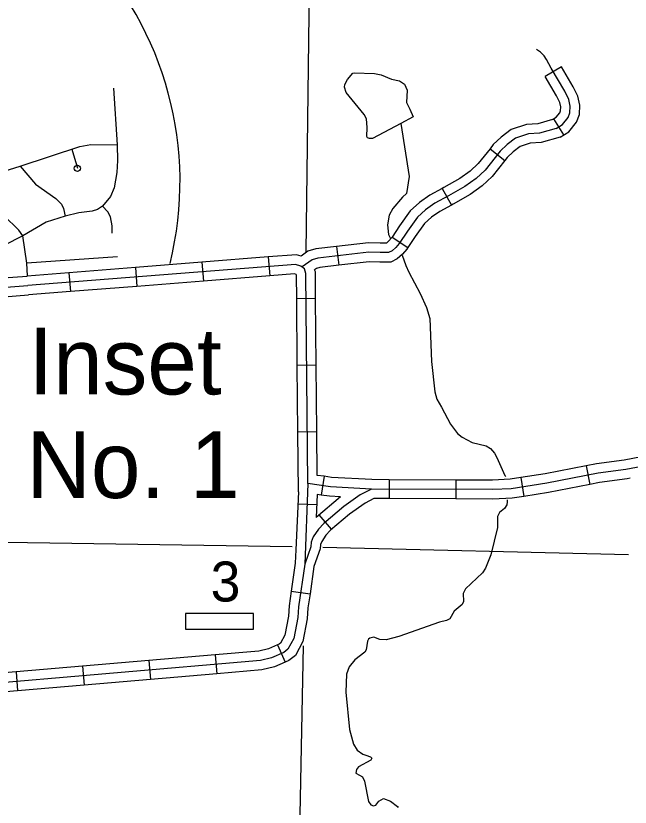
# Model space of a CAD drawing. Extents: x 1370567 to 1373900, y 377514 to 379648.
# Drawn here: x 1371923.2 to 1372062.3, y 377996 to 378175.1 of the extents above; entities that cross this region are included whole.
import ezdxf

# ---------------------------------------------------------------- set-up
doc = ezdxf.new("R2010")
doc.units = 0
doc.layers.add('Default', color=7, linetype='Continuous')

msp = doc.modelspace()

# ---------------------------------------------------------------- linework, layer by layer
at = {"layer": 'Default'}
for p, q in [((1372046.71, 378163.57), (1372043.03, 378161.37)), ((1372047.25, 378148.21), (1372044.99, 378151.85)), ((1372030.55, 378145.06), (1372033.9, 378142.39)), ((1372019.75, 378136.07), (1372021.8, 378132.31)), ((1372008.38, 378125.04), (1372011.96, 378122.68)), ((1371995.82, 378122.94), (1371996.31, 378118.68)), ((1371980.38, 378120.56), (1371980.72, 378116.28)), ((1371965.35, 378119.37), (1371965.68, 378115.1)), ((1371935.27, 378117), (1371935.6, 378112.73)), ((1371950.31, 378118.18), (1371950.64, 378113.91)), ((1371991.08, 378111.15), (1371986.8, 378111.11)), ((1371991.22, 378096.07), (1371986.93, 378096.03)), ((1371991.35, 378080.98), (1371987.06, 378080.94)), ((1372052.29, 378073.29), (1372053.12, 378069.09)), ((1371992.98, 378070.92), (1371992.37, 378066.68)), ((1372037.54, 378070.62), (1372038.19, 378066.38)), ((1372007.74, 378070.15), (1372007.72, 378065.87)), ((1372022.82, 378070.08), (1372022.8, 378065.8)), ((1371987.06, 378064.71), (1371991.34, 378064.52)), ((1371994.67, 378058.94), (1371991.91, 378062.22)), ((1371985.57, 378044.95), (1371989.81, 378044.34)), ((1371976.99, 378039.88), (1371961.63, 378039.88)), ((1371961.63, 378039.88), (1371961.63, 378036.31)), ((1371976.99, 378036.31), (1371976.99, 378039.88)), ((1371961.63, 378036.31), (1371976.99, 378036.31)), ((1371982.49, 378032.8), (1371984.18, 378028.86)), ((1371953.35, 378029.23), (1371953.72, 378024.96)), ((1371968.38, 378030.52), (1371968.75, 378026.25)), ((1371938.32, 378027.94), (1371938.68, 378023.67)), ((1371923.29, 378026.66), (1371923.65, 378022.39))]:
    msp.add_line(p, q, dxfattribs=at)
for points in [[(1371990.75, 378238.67), (1371989.89, 378205.51), (1371988.86, 378121.7)], [(1372045.54, 378149.67), (1372046.93, 378150.53), (1372048.26, 378152.11), (1372048.64, 378153.19), (1372048.7, 378154.71), (1372048.39, 378156.23), (1372047.5, 378158.06), (1372044.4, 378163.25), (1372043.33, 378165.27), (1372042.82, 378166.09), (1372042, 378166.92), (1372041.05, 378167.49)], [(1372046.41, 378147.69), (1372048.35, 378148.89), (1372050.15, 378151.03), (1372050.77, 378152.78), (1372050.85, 378154.88), (1372050.43, 378156.92), (1372049.39, 378159.08), (1372046.71, 378163.57)], [(1372010.39, 378150.78), (1372003.97, 378147.38), (1372003.27, 378147.35), (1372002.82, 378147.53), (1372002.65, 378147.82), (1372002.78, 378149.84), (1372002.57, 378151.81), (1372002.1, 378152.77), (1371997.98, 378157.8), (1371997.61, 378158.97), (1371997.71, 378159.57), (1371998.32, 378160.72), (1371999.52, 378162.17), (1371999.84, 378162.23), (1372004.41, 378162.06), (1372005.9, 378161.77), (1372008.24, 378160.79), (1372010.07, 378160.39), (1372011.17, 378159.67), (1372011.82, 378158.28), (1372011.68, 378155.48), (1372012.42, 378153.98), (1372013.13, 378152.28), (1372010.39, 378150.78), (1372012.27, 378138.8), (1372011.65, 378134.91), (1372010.73, 378134.06), (1372008.54, 378131.54), (1372007.72, 378130.01), (1372007.35, 378127.86), (1372007.54, 378125.64), (1372008.04, 378124.72)], [(1372044.67, 378151.65), (1372045.51, 378152.17), (1372046.37, 378153.19), (1372046.51, 378153.6), (1372046.55, 378154.53), (1372046.34, 378155.53), (1372045.61, 378157.04), (1372043.03, 378161.37)], [(1371945.37, 378158.76), (1371946.18, 378145.93), (1371946.25, 378142.39), (1371946.13, 378139.65), (1371945.47, 378136.24), (1371944.65, 378134.26), (1371942.89, 378132.03), (1371941.73, 378131.28), (1371940.5, 378130.92), (1371937.51, 378130.58), (1371934.42, 378129.79), (1371930.1, 378128.43), (1371924.82, 378125.37)], [(1372044.67, 378151.65), (1372041.36, 378150.72), (1372038.8, 378150.53), (1372035.31, 378149.37), (1372033.05, 378147.65), (1372031.28, 378145.98), (1372030.55, 378145.06)], [(1372045.54, 378149.67), (1372041.73, 378148.6), (1372039.22, 378148.41), (1372036.33, 378147.45), (1372034.44, 378146.01), (1372032.87, 378144.53), (1372029.46, 378140.24), (1372027.41, 378138.32), (1372024.87, 378136.51), (1372021.14, 378134.39), (1372018.05, 378132.7), (1372015.94, 378131.24), (1372014.11, 378129.55), (1372011.86, 378126.43), (1372009.99, 378123.6), (1372009.21, 378122.67), (1372008.37, 378121.94), (1372007.6, 378121.56), (1372005.66, 378121.55), (1372003.11, 378121.62), (1371991.57, 378120.3), (1371990.29, 378119.9), (1371988.06, 378118.32)], [(1372046.41, 378147.69), (1372042.11, 378146.48), (1372039.65, 378146.29), (1372037.34, 378145.53), (1372035.82, 378144.38), (1372034.45, 378143.08), (1372033.9, 378142.39)], [(1371925.86, 378116.26), (1371925.7, 378119.19), (1371924.82, 378125.37), (1371923.91, 378126.66), (1371920.56, 378129.91), (1371918.1, 378131.67), (1371913.1, 378133.47), (1371912.27, 378134.37), (1371911.72, 378135.46), (1371911.65, 378136.23), (1371912.12, 378137.07), (1371912.79, 378137.59), (1371924.21, 378141.11), (1371937.7, 378145.58), (1371940.18, 378146.02), (1371946.18, 378145.93)], [(1371935.94, 378144.92), (1371937.16, 378140.63)], [(1372030.55, 378145.06), (1372027.88, 378141.7), (1372026.05, 378139.98), (1372023.71, 378138.32), (1372020.09, 378136.26), (1372019.75, 378136.07)], [(1372033.9, 378142.39), (1372031.04, 378138.79), (1372028.77, 378136.66), (1372026.03, 378134.7), (1372022.18, 378132.51), (1372021.8, 378132.31)], [(1371924.21, 378141.11), (1371927.69, 378137.01), (1371932.26, 378133.81), (1371933.57, 378132.49), (1371934.05, 378131.5), (1371934.42, 378129.79)], [(1372019.75, 378136.07), (1372016.93, 378134.53), (1372014.59, 378132.91), (1372012.5, 378130.98), (1372010.09, 378127.64), (1372008.38, 378125.04)], [(1371945.06, 378125.96), (1371945.03, 378127.62), (1371944.65, 378129.64), (1371944.03, 378130.8), (1371942.89, 378132.03)], [(1372021.8, 378132.31), (1372019.18, 378130.88), (1372017.28, 378129.56), (1372015.72, 378128.12), (1372013.62, 378125.21), (1372011.96, 378122.68)], [(1371924.82, 378125.37), (1371920.49, 378123.18), (1371919.12, 378122.78), (1371915.24, 378122.6), (1371913.7, 378122.26), (1371907.17, 378119.97), (1371905.16, 378119.33), (1371900.12, 378116.7), (1371898.14, 378114.1)], [(1372008.38, 378125.04), (1372008.27, 378124.88), (1372007.68, 378124.18), (1372007.17, 378123.73), (1372007.09, 378123.7), (1372005.68, 378123.69), (1372003.02, 378123.76), (1371995.82, 378122.94)], [(1371995.82, 378122.94), (1371991.13, 378122.4), (1371989.33, 378121.85), (1371987.78, 378120.75)], [(1372011.96, 378122.68), (1372011.71, 378122.31), (1372010.74, 378121.16), (1372009.57, 378120.15), (1372008.11, 378119.41), (1372005.63, 378119.41), (1372003.21, 378119.47), (1371996.31, 378118.68)], [(1371946.28, 378120.62), (1371925.7, 378119.19)], [(1371980.38, 378120.56), (1371965.35, 378119.37)], [(1371987.78, 378120.75), (1371986.77, 378121.06), (1371980.38, 378120.56)], [(1372010.7, 378120.95), (1372011.46, 378118.63), (1372012.14, 378117.1), (1372014.74, 378112.32), (1372016.17, 378109.15), (1372016.91, 378106.6), (1372017.31, 378096.9), (1372018.07, 378090.04), (1372018.5, 378088.36), (1372019.56, 378086.58), (1372021.6, 378082.71), (1372023.18, 378080.6), (1372024.26, 378079.76), (1372026.54, 378078.57), (1372029.66, 378077.83), (1372030.65, 378077.19)], [(1372112.14, 378081.55), (1372108.18, 378080.85), (1372102.42, 378080.14), (1372061.25, 378072.49), (1372054.98, 378071.64), (1372043.39, 378069.35), (1372035.33, 378068.12), (1372031.16, 378067.9), (1372003.7, 378068.03), (1371994.43, 378068.55), (1371989.31, 378069.28), (1371988.89, 378116.82), (1371988.54, 378117.85), (1371987.77, 378118.51), (1371986.54, 378118.89), (1371925.97, 378114.12)], [(1371965.35, 378119.37), (1371950.31, 378118.18)], [(1371996.31, 378118.68), (1371992.01, 378118.19), (1371991.25, 378117.95), (1371990.86, 378117.68)], [(1371935.27, 378117), (1371925.8, 378116.25)], [(1371950.31, 378118.18), (1371935.27, 378117)], [(1371991.08, 378111.15), (1371991.03, 378117.18), (1371990.86, 378117.68)], [(1371919.24, 378115.74), (1371925.8, 378116.25)], [(1371965.68, 378115.1), (1371950.64, 378113.91)], [(1371980.72, 378116.28), (1371965.68, 378115.1)], [(1371986.8, 378111.11), (1371986.75, 378116.46), (1371986.7, 378116.6), (1371986.3, 378116.72), (1371980.72, 378116.28)], [(1371829.44, 378108.69), (1371831.69, 378107.62), (1371833.21, 378107.22), (1371836.44, 378107.16), (1371925.97, 378114.12)], [(1371950.64, 378113.91), (1371935.6, 378112.73)], [(1371919.57, 378111.47), (1371926.13, 378111.98)], [(1371935.6, 378112.73), (1371926.13, 378111.98)], [(1371986.93, 378096.03), (1371986.8, 378111.11)], [(1371991.22, 378096.07), (1371991.08, 378111.15)], [(1371987.06, 378080.94), (1371986.93, 378096.03)], [(1371991.35, 378080.98), (1371991.22, 378096.07)], [(1371987.18, 378067.42), (1371987.06, 378080.94)], [(1371992.98, 378070.92), (1371991.43, 378071.14), (1371991.35, 378080.98)], [(1372030.65, 378077.19), (1372031.55, 378076.18), (1372032.11, 378075.19), (1372033.93, 378071.09), (1372034.11, 378070.87)], [(1372067.19, 378075.78), (1372060.91, 378074.61), (1372054.62, 378073.75), (1372052.29, 378073.29)], [(1372052.29, 378073.29), (1372043.02, 378071.46), (1372037.54, 378070.62)], [(1372007.74, 378070.15), (1372003.77, 378070.17), (1371994.65, 378070.68), (1371992.98, 378070.92)], [(1372037.54, 378070.62), (1372035.11, 378070.25), (1372031.11, 378070.04), (1372022.82, 378070.08)], [(1372062.26, 378070.5), (1372061.59, 378070.38), (1372055.33, 378069.52), (1372053.12, 378069.09)], [(1371989.31, 378069.28), (1371988.61, 378051.03)], [(1372022.82, 378070.08), (1372007.74, 378070.15)], [(1372053.12, 378069.09), (1372043.76, 378067.23), (1372038.19, 378066.38)], [(1372003.7, 378068.03), (1372001.15, 378066.7), (1371997.43, 378064.06), (1371992.93, 378060.27), (1371991.7, 378058.94), (1371990.56, 378057.2), (1371990.06, 378056.02), (1371989.97, 378054.97), (1371988.61, 378051.03), (1371987.22, 378041.36), (1371987.03, 378038.96), (1371986.12, 378034.23), (1371984.82, 378031.79), (1371983.92, 378031.08), (1371981.09, 378029.86), (1371978.58, 378029.25), (1371911.98, 378023.53)], [(1371987.18, 378067.42), (1371986.59, 378054.29)], [(1371991.44, 378066.81), (1371991.21, 378061.63)], [(1371992.37, 378066.68), (1371991.44, 378066.81)], [(1371996.73, 378066.27), (1371994.22, 378066.41), (1371992.37, 378066.68)], [(1371996.73, 378066.27), (1371991.21, 378061.63)], [(1372004.22, 378065.88), (1372002.27, 378064.87), (1371998.74, 378062.37), (1371994.41, 378058.72), (1371993.31, 378057.52)], [(1372034.42, 378065.63), (1372034.44, 378065.16), (1372034.37, 378064.47), (1372033.84, 378063.61), (1372032.71, 378062.76), (1372032.24, 378061.84), (1372032.26, 378059.33), (1372030.72, 378053.16), (1372029.54, 378050.12), (1372028.82, 378049.08), (1372025.03, 378045.44), (1372024.45, 378044.4), (1372024.51, 378042.58), (1372024.21, 378041.94), (1372022.41, 378040.4), (1372021.44, 378038.64), (1372020.68, 378038.26), (1372019.08, 378037.91), (1372009.94, 378034.64), (1372007.01, 378033.93), (1372005.58, 378033.99), (1372004.23, 378034.53), (1372003.38, 378034.32), (1372003.07, 378034.08), (1372002.85, 378033.6), (1372002.51, 378031.68), (1372002.24, 378031.13), (1371999.92, 378029.4), (1371998.7, 378027.81), (1371998.07, 378026.15), (1371997.92, 378022.06), (1371998.76, 378013.63), (1371999.62, 378010.33), (1372000.47, 378008.98), (1372001.75, 378008.06), (1372002.41, 378007.84)], [(1372007.72, 378065.87), (1372004.22, 378065.88)], [(1372022.8, 378065.8), (1372007.72, 378065.87)], [(1372038.19, 378066.38), (1372035.55, 378065.98), (1372031.21, 378065.75), (1372022.8, 378065.8)], [(1371818.44, 378057.56), (1371836.04, 378057.27), (1371985.75, 378055.03)], [(1371993.39, 378057.61), (1371992.46, 378056.19), (1371992.17, 378055.5), (1371992.08, 378054.52), (1371990.7, 378050.53), (1371989.81, 378044.34)], [(1371986.59, 378054.29), (1371986.48, 378051.23)], [(1371992.7, 378054.9), (1372061.86, 378053.2)], [(1371986.48, 378051.23), (1371985.57, 378044.95)], [(1371985.57, 378044.95), (1371985.09, 378041.6), (1371984.91, 378039.25), (1371984.08, 378034.96), (1371983.15, 378033.19), (1371982.82, 378032.94), (1371982.49, 378032.8)], [(1371989.81, 378044.34), (1371989.35, 378041.13), (1371989.16, 378038.67), (1371988.16, 378033.51), (1371986.5, 378030.38), (1371985.02, 378029.22), (1371984.18, 378028.86)], [(1371982.49, 378032.8), (1371980.4, 378031.9), (1371978.24, 378031.37), (1371968.38, 378030.52)], [(1371988.24, 378032.57), (1371987.17, 377979), (1371988.15, 377927.13)], [(1371953.35, 378029.23), (1371938.32, 378027.94)], [(1371968.38, 378030.52), (1371953.35, 378029.23)], [(1371938.32, 378027.94), (1371923.29, 378026.66)], [(1371984.18, 378028.86), (1371981.77, 378027.82), (1371978.93, 378027.13), (1371968.75, 378026.25)], [(1371923.29, 378026.66), (1371911.82, 378025.67), (1371908.3, 378025.45)], [(1371968.75, 378026.25), (1371953.72, 378024.96)], [(1371938.68, 378023.67), (1371923.65, 378022.39)], [(1371953.72, 378024.96), (1371938.68, 378023.67)], [(1371923.65, 378022.39), (1371912.14, 378021.4), (1371908.57, 378021.17)], [(1372002.41, 378007.84), (1372003.5, 378007.44), (1372003.79, 378007.16), (1372003.54, 378006.67), (1372000.8, 378005.16), (1372000.32, 378004.55), (1372000.2, 378003.75), (1372001.03, 378003.25), (1372001.67, 378002.89), (1372002.17, 378001.96), (1372003.06, 377997.3), (1372003.61, 377996.59), (1372004.19, 377996.38), (1372004.67, 377996.53), (1372005.4, 377997.4), (1372006.42, 377998.01), (1372008.03, 377997.39), (1372009.59, 377996.19), (1372009.74, 377995.99)]]:
    msp.add_lwpolyline(points, dxfattribs=at)
msp.add_circle((1371937.16, 378140.63), 0.714, dxfattribs=at)
msp.add_arc((1371883.64, 378137.62), 76.76, 346.0467, 102.2496, dxfattribs=at)

# ---------------------------------------------------------------- texts
for s, height, p in [('Inset', 15.086, (1371926.08, 378089.44)), ('No. 1', 15.086, (1371925.66, 378066.01)), ('3', 9.05, (1371967.33, 378042.59))]:
    msp.add_text(s, height=height, dxfattribs=at).set_placement(p)

doc.saveas('drawing.dxf')
